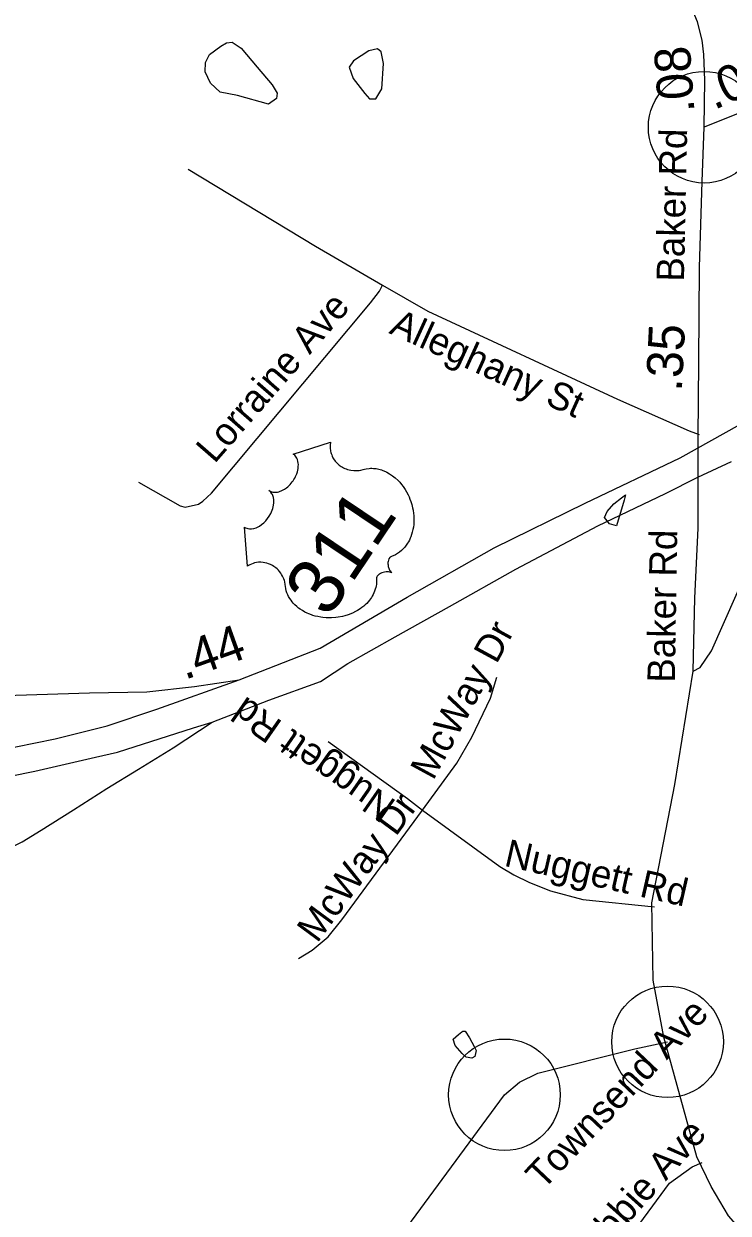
# Model space of a CAD drawing. Extents: x 1715610 to 1720914, y 798298 to 802505.
# Drawn here: x 1715906.1 to 1715959.1, y 799485.2 to 799574.8 of the extents above; entities that cross this region are included whole.
import ezdxf

# ---------------------------------------------------------------- set-up
doc = ezdxf.new("R2010")
doc.units = 0
doc.layers.add('Default', color=7, linetype='Continuous')
doc.layers.add('Prop DSN Text', color=7, linetype='Continuous')

msp = doc.modelspace()

# ---------------------------------------------------------------- linework, layer by layer
at = {"layer": 'Default'}
for points in [[(1715957.296, 799566.997), (1715957.344, 799570.543), (1715957.268, 799572.462), (1715957.145, 799573.549), (1715956.782, 799574.938), (1715956.346, 799576.012)], [(1715941.493, 799535.312), (1715948.343, 799538.678), (1715955.479, 799542.102), (1715960.037, 799544.642), (1715964.106, 799546.266), (1715968.098, 799547.732), (1715972.121, 799548.843), (1715978.623, 799550.131), (1715981.662, 799550.655), (1715985.351, 799551.464), (1715989.314, 799552.485), (1715991.764, 799553.402), (1715994.895, 799554.848), (1715997.846, 799556.414), (1716000.116, 799557.846), (1716002.189, 799559.278), (1716003.673, 799560.515), (1716005.05, 799561.495), (1716007.669, 799563.939), (1716010.638, 799567.002), (1716012.471, 799569.251), (1716014.517, 799572.209), (1716016.2, 799575.018)], [(1715924.497, 799568.742), (1715922.159, 799569.383), (1715920.871, 799569.648), (1715920.122, 799570.312), (1715919.724, 799571.176), (1715919.75, 799571.864), (1715920.052, 799572.477), (1715920.904, 799573.101), (1715921.342, 799573.351), (1715921.755, 799573.4), (1715922.429, 799572.949), (1715923.652, 799571.533), (1715924.763, 799570.192), (1715925.149, 799569.554), (1715925.098, 799569.153), (1715924.497, 799568.742)], [(1715932.06, 799572.745), (1715930.908, 799571.997), (1715930.582, 799571.509), (1715930.88, 799570.658), (1715931.754, 799569.531), (1715932.091, 799569.142), (1715932.578, 799569.141), (1715933.018, 799569.879), (1715933.159, 799571.793), (1715932.986, 799572.669), (1715932.711, 799572.907), (1715932.06, 799572.745)], [(1715962.744, 799569.192), (1715957.296, 799566.997)], [(1715956.471, 799526.044), (1715956.496, 799527.158), (1715956.59, 799531.545), (1715956.852, 799536.795), (1715956.837, 799543.619), (1715956.893, 799549.35), (1715956.955, 799556.425), (1715957.133, 799562.915), (1715957.296, 799566.997)], [(1715918.445, 799563.832), (1715928.036, 799558.045), (1715933.081, 799555.093)], [(1715914.717, 799540.273), (1715917.843, 799538.485), (1715918.214, 799538.394), (1715919.228, 799538.608), (1715919.544, 799538.842), (1715920.219, 799539.44), (1715932.167, 799553.762), (1715932.859, 799554.652), (1715933.081, 799555.093)], [(1715933.081, 799555.093), (1715936.502, 799553.144), (1715950.76, 799546.519), (1715956.155, 799544.125), (1715956.918, 799543.859)], [(1715956.471, 799526.044), (1715956.999, 799526.322), (1715957.841, 799527.579), (1715962.552, 799538.152), (1715963.945, 799541.074), (1715967.073, 799546.062), (1715968.694, 799548.248), (1715969.224, 799548.606), (1715969.814, 799548.659)], [(1715956.826, 799540.652), (1715959.355, 799541.83)], [(1715943.112, 799533.722), (1715949.291, 799536.989), (1715954.394, 799539.409), (1715956.826, 799540.652)], [(1715950.691, 799536.99), (1715950.164, 799537.142), (1715949.794, 799537.604), (1715949.992, 799538.048), (1715950.506, 799538.646), (1715951.078, 799539.098), (1715951.383, 799539.313), (1715951.269, 799538.914), (1715950.691, 799536.99)], [(1715922.285, 799525.387), (1715928.394, 799527.778), (1715934.927, 799531.619), (1715941.493, 799535.312)], [(1715920.265, 799522.194), (1715924.52, 799523.853), (1715928.402, 799525.26), (1715930.48, 799526.603), (1715934.036, 799528.626), (1715938.115, 799530.899), (1715943.112, 799533.722)], [(1715891.357, 799523.768), (1715894.606, 799523.709), (1715898.493, 799523.733), (1715901.79, 799523.961), (1715905.47, 799524.229), (1715911.016, 799524.405), (1715915.338, 799524.48), (1715918.937, 799524.876), (1715922.285, 799525.387)], [(1715892.293, 799518.75), (1715898.302, 799519.127), (1715903.977, 799520.048), (1715908.426, 799520.93), (1715912.342, 799521.913), (1715916.1, 799523.174), (1715922.285, 799525.387)], [(1715936.103, 799515.559), (1715938.683, 799519.099), (1715939.796, 799521.057), (1715941.22, 799523.996), (1715941.7, 799525.573)], [(1716023.718, 799419.386), (1716016.126, 799426.487), (1716009.969, 799432.19), (1716003.784, 799437.668), (1715996.928, 799443.961), (1715992.338, 799448.007), (1715990.609, 799449.635), (1715988.316, 799452.217), (1715982.034, 799460.209), (1715980.122, 799463.74), (1715978.992, 799465.379), (1715977.581, 799467.165), (1715976.083, 799468.756), (1715974.189, 799470.715), (1715970.305, 799473.958), (1715962.149, 799481.58), (1715959.118, 799485.028), (1715957.834, 799487.223), (1715956.743, 799489.456), (1715954.262, 799498.464), (1715953.463, 799502.756), (1715953.361, 799508.585), (1715955.096, 799517.509), (1715956.471, 799526.044)], [(1715892.752, 799516.578), (1715899.144, 799517.159), (1715903.29, 799517.782), (1715906.899, 799518.498), (1715911.475, 799519.566), (1715913.119, 799519.932), (1715918.844, 799521.764), (1715920.265, 799522.194)], [(1715893.84, 799510.912), (1715896.963, 799510.94), (1715898.053, 799510.977), (1715899.691, 799511.207), (1715901.162, 799511.395), (1715902.107, 799511.662), (1715902.975, 799511.914), (1715904.618, 799512.54), (1715905.955, 799513.183), (1715907.391, 799514.074), (1715909.811, 799515.602), (1715912.335, 799517.21), (1715914.709, 799518.668), (1715917.326, 799520.264), (1715920.265, 799522.194)], [(1715928.999, 799520.752), (1715934.964, 799516.446), (1715936.103, 799515.559)], [(1715926.758, 799504.409), (1715927.781, 799505.027), (1715928.997, 799506.022), (1715930.016, 799507.319), (1715936.103, 799515.559)], [(1715936.103, 799515.559), (1715941.919, 799511.339), (1715942.977, 799510.703), (1715944.142, 799510.126), (1715945.717, 799509.491), (1715948.161, 799508.842), (1715953.568, 799508.279)], [(1715939.135, 799498.936), (1715939.293, 799498.935), (1715939.637, 799498.437), (1715939.979, 799497.779), (1715940.132, 799497.464), (1715940.032, 799497.008), (1715939.799, 799496.901), (1715939.379, 799496.978), (1715939.08, 799497.234), (1715938.557, 799497.858), (1715938.404, 799498.328), (1715938.808, 799498.688), (1715939.051, 799498.888), (1715939.135, 799498.936)], [(1715939.135, 799498.936), (1715939.293, 799498.935), (1715939.637, 799498.437), (1715939.979, 799497.779), (1715940.132, 799497.464), (1715940.032, 799497.008), (1715939.799, 799496.901), (1715939.379, 799496.978), (1715939.08, 799497.234), (1715938.557, 799497.858), (1715938.404, 799498.328), (1715938.808, 799498.688), (1715939.051, 799498.888), (1715939.135, 799498.936)], [(1715915.48, 799450.355), (1715920.398, 799460.057), (1715922.102, 799463.589), (1715923.37, 799467.369), (1715924.004, 799468.869), (1715924.795, 799470.289), (1715926.931, 799473.286), (1715942.26, 799494.135), (1715943.397, 799495.085), (1715944.774, 799495.776), (1715952.083, 799497.604), (1715954.539, 799498.123)], [(1715948.254, 799478.735), (1715954.691, 799487.47), (1715956.39, 799488.718), (1715957.146, 799489.036)]]:
    msp.add_lwpolyline(points, dxfattribs=at)
msp.add_lwpolyline([(1715922.685, 799536.885), (1715922.768, 799536.837), (1715922.875, 799536.793), (1715922.933, 799536.775), (1715923.056, 799536.757), (1715923.215, 799536.756), (1715923.391, 799536.786), (1715923.561, 799536.837), (1715923.663, 799536.881), (1715923.821, 799536.965), (1715923.983, 799537.072), (1715924.142, 799537.205), (1715924.289, 799537.352), (1715924.433, 799537.523), (1715924.559, 799537.703), (1715924.676, 799537.911), (1715924.78, 799538.157), (1715924.821, 799538.275), (1715924.858, 799538.413), (1715924.885, 799538.546), (1715924.9, 799538.702), (1715924.903, 799538.833), (1715924.898, 799538.94), (1715924.869, 799539.108), (1715924.822, 799539.257), (1715924.789, 799539.329), (1715924.754, 799539.395), (1715924.665, 799539.512), (1715924.621, 799539.558), (1715924.521, 799539.637), (1715924.614, 799539.584), (1715924.676, 799539.556), (1715924.74, 799539.534), (1715924.813, 799539.518), (1715924.922, 799539.504), (1715925.021, 799539.504), (1715925.179, 799539.522), (1715925.265, 799539.542), (1715925.337, 799539.564), (1715925.514, 799539.635), (1715925.694, 799539.735), (1715925.777, 799539.788), (1715925.856, 799539.847), (1715925.95, 799539.925), (1715926.042, 799540.01), (1715926.126, 799540.099), (1715926.209, 799540.191), (1715926.287, 799540.29), (1715926.346, 799540.373), (1715926.414, 799540.479), (1715926.473, 799540.579), (1715926.528, 799540.685), (1715926.583, 799540.806), (1715926.622, 799540.906), (1715926.669, 799541.043), (1715926.701, 799541.172), (1715926.723, 799541.291), (1715926.74, 799541.451), (1715926.745, 799541.588), (1715926.735, 799541.697), (1715926.714, 799541.832), (1715926.675, 799541.973), (1715926.639, 799542.064), (1715926.592, 799542.144), (1715926.54, 799542.223), (1715926.475, 799542.293), (1715926.414, 799542.347), (1715926.358, 799542.387), (1715929.175, 799543.284), (1715929.162, 799543.227), (1715929.143, 799543.089), (1715929.136, 799542.973), (1715929.141, 799542.779), (1715929.154, 799542.688), (1715929.169, 799542.595), (1715929.191, 799542.505), (1715929.214, 799542.424), (1715929.254, 799542.316), (1715929.297, 799542.215), (1715929.35, 799542.109), (1715929.4, 799542.024), (1715929.515, 799541.861), (1715929.593, 799541.768), (1715929.664, 799541.694), (1715929.82, 799541.557), (1715929.898, 799541.496), (1715929.979, 799541.442), (1715930.067, 799541.39), (1715930.154, 799541.343), (1715930.249, 799541.301), (1715930.333, 799541.264), (1715930.441, 799541.227), (1715930.57, 799541.189), (1715930.702, 799541.162), (1715930.927, 799541.138), (1715931.173, 799541.137), (1715931.322, 799541.154), (1715931.457, 799541.179), (1715931.637, 799541.231), (1715931.736, 799541.257), (1715931.859, 799541.281), (1715932.08, 799541.308), (1715932.178, 799541.313), (1715932.285, 799541.312), (1715932.391, 799541.307), (1715932.503, 799541.298), (1715932.599, 799541.286), (1715932.809, 799541.243), (1715933.002, 799541.186), (1715933.101, 799541.152), (1715933.314, 799541.062), (1715933.416, 799541.013), (1715933.61, 799540.905), (1715933.832, 799540.756), (1715934.032, 799540.598), (1715934.252, 799540.393), (1715934.377, 799540.262), (1715934.515, 799540.097), (1715934.631, 799539.948), (1715934.791, 799539.714), (1715934.898, 799539.53), (1715935.017, 799539.304), (1715935.083, 799539.16), (1715935.149, 799538.999), (1715935.22, 799538.805), (1715935.289, 799538.588), (1715935.349, 799538.342), (1715935.387, 799538.151), (1715935.421, 799537.912), (1715935.435, 799537.771), (1715935.446, 799537.576), (1715935.446, 799537.32), (1715935.43, 799537.078), (1715935.406, 799536.878), (1715935.375, 799536.709), (1715935.326, 799536.495), (1715935.214, 799536.159), (1715935.167, 799536.042), (1715935.103, 799535.907), (1715935.038, 799535.785), (1715934.97, 799535.669), (1715934.87, 799535.519), (1715934.759, 799535.378), (1715934.644, 799535.251), (1715934.516, 799535.125), (1715934.368, 799535.002), (1715934.22, 799534.9), (1715934.057, 799534.806), (1715933.748, 799534.668), (1715933.666, 799534.624), (1715933.63, 799534.592), (1715933.564, 799534.503), (1715933.524, 799534.405), (1715933.5, 799534.293), (1715933.493, 799534.221), (1715933.492, 799534.118), (1715933.499, 799534.035), (1715933.517, 799533.928), (1715933.539, 799533.847), (1715933.557, 799533.785), (1715933.617, 799533.648), (1715933.651, 799533.59), (1715933.699, 799533.522), (1715933.78, 799533.437), (1715933.639, 799533.487), (1715933.536, 799533.505), (1715933.441, 799533.509), (1715933.352, 799533.507), (1715933.23, 799533.492), (1715933.132, 799533.471), (1715933.025, 799533.437), (1715932.926, 799533.391), (1715932.853, 799533.351), (1715932.794, 799533.309), (1715932.73, 799533.251), (1715932.688, 799533.197), (1715932.658, 799533.15), (1715932.63, 799533.076), (1715932.634, 799532.947), (1715932.636, 799532.827), (1715932.631, 799532.7), (1715932.617, 799532.556), (1715932.601, 799532.453), (1715932.575, 799532.336), (1715932.538, 799532.202), (1715932.49, 799532.064), (1715932.432, 799531.927), (1715932.378, 799531.808), (1715932.312, 799531.687), (1715932.246, 799531.582), (1715932.173, 799531.475), (1715932.097, 799531.379), (1715932.009, 799531.269), (1715931.89, 799531.138), (1715931.782, 799531.036), (1715931.663, 799530.932), (1715931.535, 799530.829), (1715931.388, 799530.725), (1715931.195, 799530.601), (1715931.051, 799530.521), (1715930.813, 799530.403), (1715930.507, 799530.283), (1715930.256, 799530.205), (1715930.061, 799530.156), (1715929.752, 799530.098), (1715929.559, 799530.072), (1715929.229, 799530.05), (1715928.999, 799530.047), (1715928.836, 799530.055), (1715928.582, 799530.078), (1715928.427, 799530.1), (1715928.208, 799530.141), (1715928.014, 799530.188), (1715927.835, 799530.239), (1715927.724, 799530.277), (1715927.535, 799530.35), (1715927.403, 799530.407), (1715927.229, 799530.492), (1715927.051, 799530.593), (1715926.894, 799530.695), (1715926.768, 799530.786), (1715926.627, 799530.902), (1715926.484, 799531.034), (1715926.367, 799531.157), (1715926.287, 799531.251), (1715926.194, 799531.372), (1715926.097, 799531.515), (1715926.012, 799531.663), (1715925.947, 799531.795), (1715925.885, 799531.947), (1715925.838, 799532.086), (1715925.797, 799532.256), (1715925.768, 799532.423), (1715925.755, 799532.568), (1715925.72, 799532.752), (1715925.693, 799532.854), (1715925.648, 799532.985), (1715925.6, 799533.098), (1715925.554, 799533.193), (1715925.48, 799533.327), (1715925.42, 799533.418), (1715925.32, 799533.549), (1715925.244, 799533.632), (1715925.142, 799533.733), (1715925.042, 799533.821), (1715924.908, 799533.919), (1715924.793, 799533.991), (1715924.65, 799534.065), (1715924.506, 799534.125), (1715924.375, 799534.17), (1715924.216, 799534.207), (1715924.093, 799534.226), (1715923.918, 799534.237), (1715923.747, 799534.233), (1715923.595, 799534.212), (1715923.453, 799534.184), (1715923.334, 799534.145), (1715923.227, 799534.105), (1715923.102, 799534.047), (1715922.993, 799533.984), (1715922.929, 799533.94)], close=True, dxfattribs=at)
at = {"layer": 'Prop DSN Text'}
for centre in [(1715957.296, 799566.997), (1715954.539, 799498.123), (1715942.26, 799494.135)]:
    msp.add_circle(centre, 4.2, dxfattribs=at)

# ---------------------------------------------------------------- texts
at = {"layer": 'Default'}
for s, height, rotation, p in [('.08', 2.7188, 94.10402, (1715956.574, 799568.15)), ('.05', 2.7188, 23.87624, (1715958.05, 799568.279)), ('Baker Rd', 2.0663, 88.7702, (1715955.774, 799555.354)), ('Lorraine Ave', 2.06625, 48.91699, (1715920.43, 799541.606)), ('Alleghany St', 2.06625, 335.53821, (1715933.498, 799551.51)), ('.35', 2.7188, 87.10766, (1715955.61, 799547.066)), ('311', 4.2413, 56.20506, (1715928.997, 799529.942)), ('Baker Rd', 2.0663, 89.09557, (1715955.087, 799525.159)), ('.44', 2.7188, 19.68883, (1715918.198, 799525.368)), ('McWay Dr', 2.0663, 61.46756, (1715936.894, 799517.747)), ('Nuggett Rd', 2.0663, 145.14475, (1715934.209, 799516.213)), ('McWay Dr', 2.0663, 53.60524, (1715928.16, 799505.499)), ('Nuggett Rd', 2.0663, 347.23861, (1715942.163, 799511.391)), ('Townsend Ave', 2.06625, 46.51082, (1715945.173, 799486.901)), ('Abbie Ave', 2.0663, 48.06984, (1715949.168, 799481.769))]:
    msp.add_text(s, height=height, rotation=rotation, dxfattribs=at).set_placement(p)

doc.saveas('drawing.dxf')
